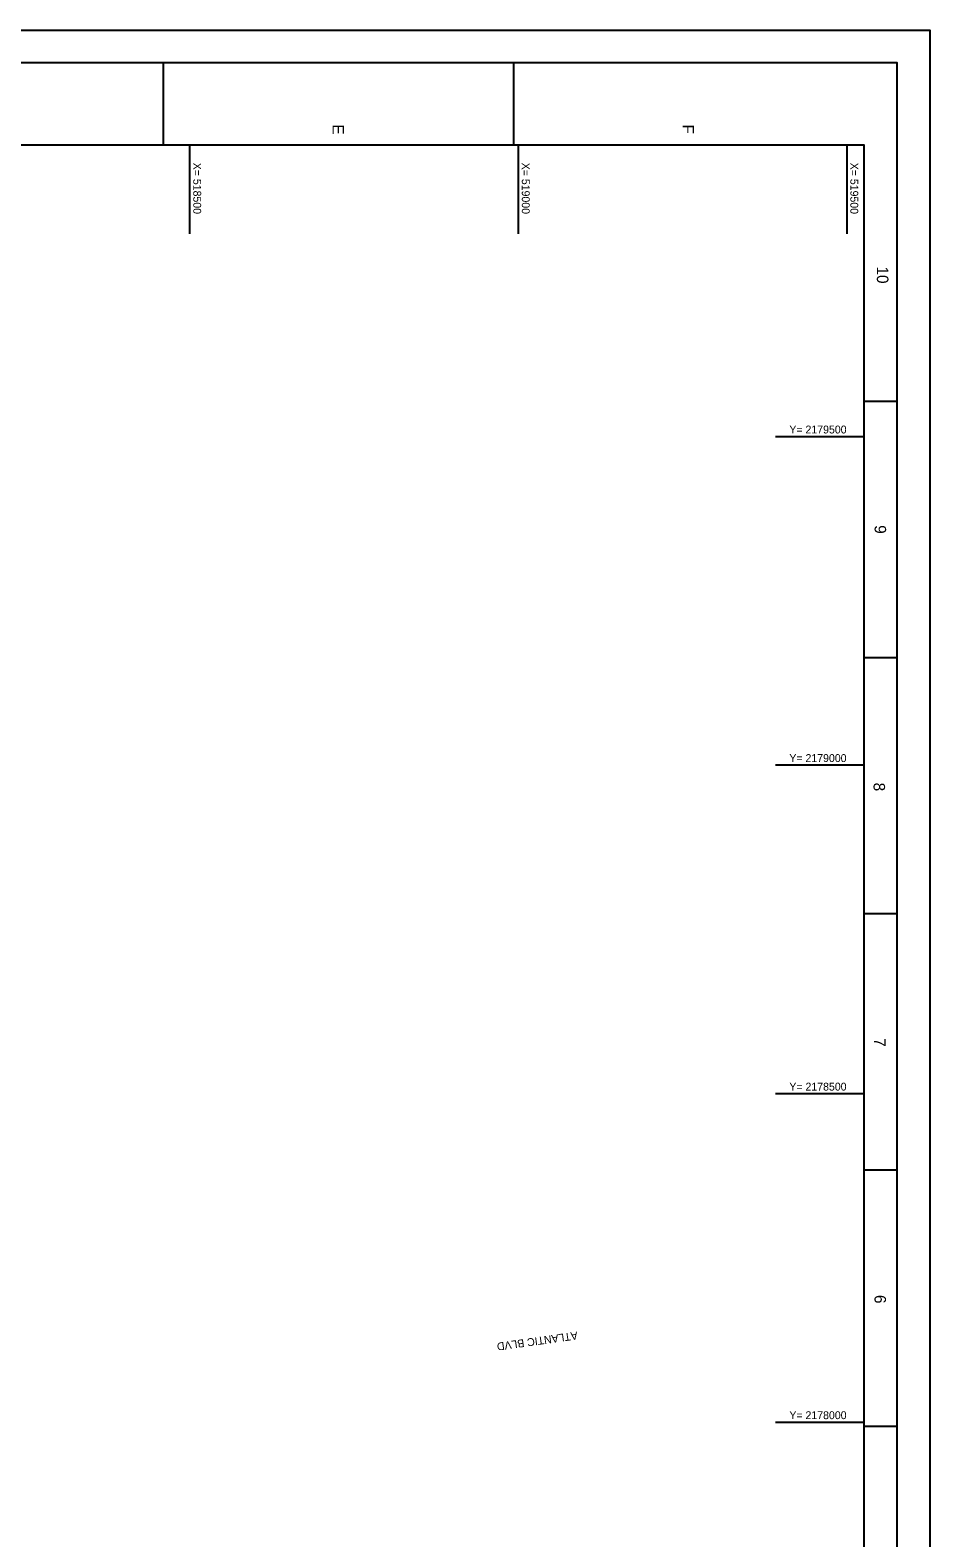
# Model space of a CAD drawing. Extents: x 516226 to 519626, y 2175719 to 2180119.
# Drawn here: x 518257 to 519626, y 2177824 to 2180119 of the extents above; entities that cross this region are included whole.
import ezdxf

# ---------------------------------------------------------------- set-up
doc = ezdxf.new("R2010")
doc.units = 0
for name, color, linetype in [('G-ANNO-NPLT', 7, 'Continuous'), ('G-ANNO-TTLB', 7, 'Continuous'), ('V-ROAD-IDEN', 7, 'Continuous'), ('V-TOPO-COOR-STAT', 7, 'Continuous')]:
    doc.layers.add(name, color=color, linetype=linetype)

msp = doc.modelspace()

# ---------------------------------------------------------------- linework, layer by layer
at = {"layer": 'G-ANNO-NPLT'}
msp.add_lwpolyline([(519626, 2180118.8), (519626, 2175718.8), (516226, 2175718.8), (516226, 2180118.8)], close=True, dxfattribs=at)
msp.add_lwpolyline([(519576, 2180118.8), (519626, 2180118.8), (519626, 2180068.8)], dxfattribs=at)
at = {"layer": 'G-ANNO-TTLB'}
for p, q in [((518459.2, 2180068.8), (518459.2, 2179943.8)), ((518992.5, 2180068.8), (518992.5, 2179943.8)), ((519576, 2179553.8), (519526, 2179553.8)), ((519576, 2179163.8), (519526, 2179163.8)), ((519576, 2179163.8), (519526, 2179163.8)), ((519576, 2178773.8), (519526, 2178773.8)), ((519576, 2178383.8), (519526, 2178383.8)), ((519576, 2177993.8), (519526, 2177993.8))]:
    msp.add_line(p, q, dxfattribs=at)
for points in [[(516276, 2180068.8), (516276, 2175768.8), (519576, 2175768.8), (519576, 2180068.8)], [(519526, 2175818.8), (519526, 2179943.8), (516326, 2179943.8), (516326, 2175818.8)]]:
    msp.add_lwpolyline(points, close=True, dxfattribs=at)
at = {"layer": 'V-TOPO-COOR-STAT'}
for p, q in [((518500, 2179808.8), (518500, 2179943.8)), ((519000, 2179808.8), (519000, 2179943.8)), ((519500, 2179808.8), (519500, 2179943.8)), ((519526, 2179500), (519391, 2179500)), ((519526, 2179000), (519391, 2179000)), ((519526, 2178500), (519391, 2178500)), ((519526, 2178000), (519391, 2178000))]:
    msp.add_line(p, q, dxfattribs=at)

# ---------------------------------------------------------------- texts
at = {"layer": 'G-ANNO-TTLB'}
for s, p in [('E', (518716.9, 2179975.3)), ('F', (519249.6, 2179975.2)), ('10', (519545.4, 2179759.2)), ('9', (519541.9, 2179365.4)), ('8', (519540.3, 2178973.6)), ('7', (519541, 2178584.9)), ('6', (519541.7, 2178194))]:
    msp.add_text(s, height=17.5, rotation=270, dxfattribs=at).set_placement(p)
at = {"layer": 'V-ROAD-IDEN'}
msp.add_text('ATLANTIC BLVD', height=12, rotation=188.0616, dxfattribs=at).set_placement((519089.1, 2178138.4))
at = {"layer": 'V-TOPO-COOR-STAT'}
for s, p in [('X= 518500', (518505, 2179917)), ('X= 519000', (519005, 2179917)), ('X= 519500', (519505, 2179917))]:
    msp.add_text(s, height=12, rotation=270, dxfattribs=at).set_placement(p)
for s, p in [('Y= 2179500', (519412.2, 2179505)), ('Y= 2179000', (519412.2, 2179005)), ('Y= 2178500', (519412.2, 2178505)), ('Y= 2178000', (519412.2, 2178005))]:
    msp.add_text(s, height=12, dxfattribs=at).set_placement(p)

doc.saveas('drawing.dxf')
